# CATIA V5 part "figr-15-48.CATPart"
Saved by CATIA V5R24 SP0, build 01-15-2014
Part number: Part1
Bounding box of the stored display mesh (mm): x 0 to 69.121, y -21.475 to 20.775, z 0 to 47.185
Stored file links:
  D:\KAVITA\CATIA V5-6R2014 Project_ Kavita\CATIA V5-6R2014_partfiles\Partfiles\c15_catia_v5-6r2014_prt\figr-15-48.CATPart
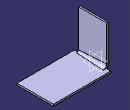
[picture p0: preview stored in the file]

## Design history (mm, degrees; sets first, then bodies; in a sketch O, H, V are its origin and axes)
SheetMetalParameters1: Thickness 2, BendRadius 4, KFactor 0.400515 {= log(min(100,max(20*SheetMetalParameters1.BendRadius,SheetMetalParameters1.Thickness)/SheetMetalParameters1.Thickness))/log(100)/2}, ReliefRadialLength 1, ReliefAxialLength 2, MinimumBendRadius 0
Body1 (main body)
  Sketch1 on xy-plane, origin (0, 0, 0), H (1, 0, 0), V (0, 1, 0)
    line L1 (2.4998, 20.7748) -> (69.1212, 20.7748)
    line L2 (69.1212, 20.7748) -> (69.1212, -21.4753)
    line L3 (69.1212, -21.4753) -> (2.4998, -21.4753)
    line L4 (2.4998, -21.4753) -> (2.4998, 20.7748)
    horizontal: L1 H, L3 H
    vertical: L2 V, L4 V
  Wall1: Thickness 2, Profile Sketch1
  Sketch2 on yz-plane, origin (0, 0, 0), H (0, 1, 0), V (0, 0, 1)
    line L1 (-17.3994, 47.1851) -> (15.4124, 47.1851)
    line L2 (15.4124, 47.1851) -> (15.4124, 3.5135)
    line L3 (15.4124, 3.5135) -> (-17.3994, 3.5135)
    line L4 (-17.3994, 3.5135) -> (-17.3994, 47.1851)
    horizontal: L1 H, L3 H
    vertical: L2 V, L4 V
  Wall2: Thickness 2, Profile Sketch2
  d_Bend1: Bend_Thickness 2, Bend_KFactor 0.36928 {= log(min(100,max(20*d_Bend1.Bend_KFactorRadius,SheetMetalParameters1.Thickness)/SheetMetalParameters1.Thickness))/log(100)/2}, Bend_FirstSupport Wall1, Bend_SecondSupport Wall2, Bend_KFactorRadius 3 {= ( d_Bend1.ConicalBendSurf_FirstRadius + d_Bend1.ConicalBendSurf_SecondRadius ) / 2.0}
